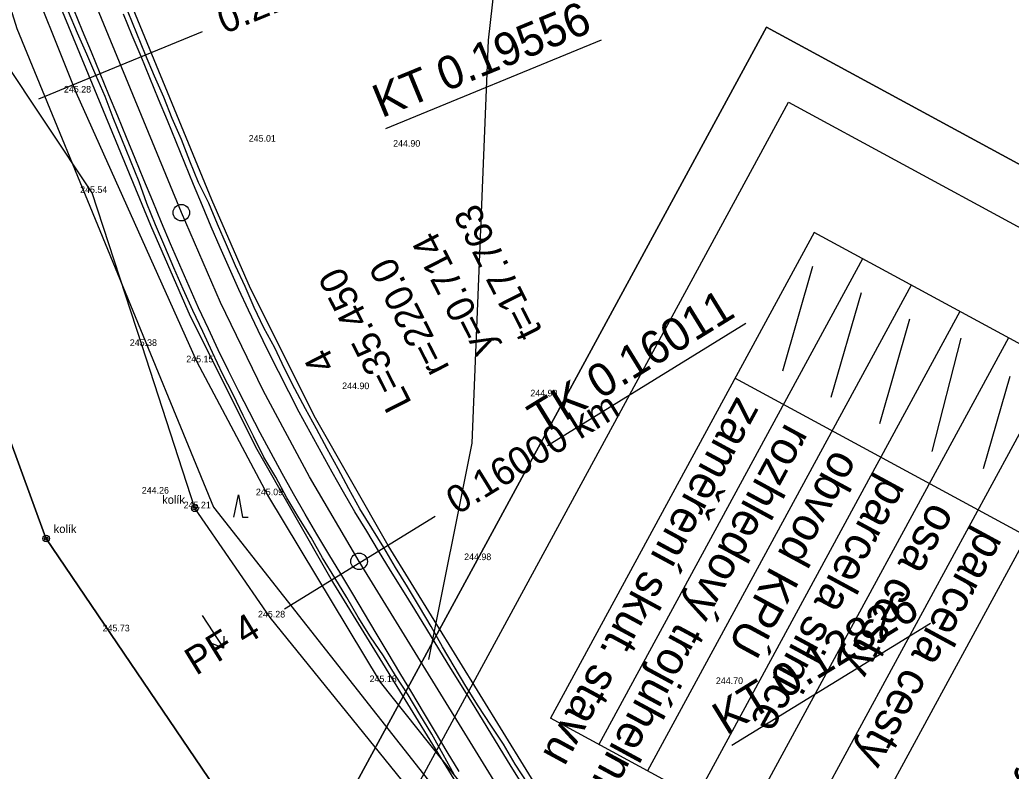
# Model space of a CAD drawing. Extents: x -555887 to -552101, y -1100251 to -1096546.
# Drawn here: x -554132.8 to -554043.2, y -1097201.2 to -1097133.2 of the extents above; entities that cross this region are included whole.
import ezdxf

# ---------------------------------------------------------------- set-up
doc = ezdxf.new("R2010")
doc.units = 0
for name, color, linetype in [('PARCELY_cesty', 7, 'Continuous'), ('PARCELY_VHO', 7, 'Continuous'), ('POLYGONY_SITUACE_PF', 7, 'Continuous'), ('POLYGONY_SITUACE_PF_POPISY', 7, 'Continuous'), ('POLYGONY_SITUACE_PO', 7, 'Continuous'), ('ROZHLED_ram_legenda_1', 7, 'Continuous'), ('vrstevnice', 7, 'Continuous'), ('Výškopis', 7, 'Continuous'), ('ZSST', 7, 'Continuous'), ('zájem', 7, 'Continuous')]:
    doc.layers.add(name, color=color, linetype=linetype)

msp = doc.modelspace()

# ---------------------------------------------------------------- linework, layer by layer
for p, q in [((-554099.718, -1097143.003), (-554080.214, -1097134.973)), ((-554085.106, -1097171.688), (-554067.143, -1097160.633)), ((-554068.416, -1097198.809), (-554050.452, -1097187.754))]:
    msp.add_line(p, q)
at = {"layer": 'PARCELY_cesty'}
for points in [[(-554039.52, -1097311.76), (-554047.31, -1097302.68), (-554067.59, -1097264.38), (-554070.02, -1097259.26), (-554071.42, -1097254.1), (-554072.18, -1097247.42), (-554073.837, -1097234.701), (-554074.64, -1097229.027), (-554076.858, -1097220.767), (-554079.626, -1097213.575), (-554082.86, -1097207.774), (-554099.501, -1097180.734), (-554106.075, -1097169.208), (-554111.955, -1097157.47), (-554115.449, -1097149.447), (-554124.686, -1097127.011)], [(-554038.74, -1097323.54), (-554046.65, -1097316.45), (-554056.115, -1097302.24), (-554073.622, -1097267.292), (-554075.994, -1097261.695), (-554077.187, -1097257.67), (-554078.248, -1097251.684), (-554079.797, -1097235.406), (-554080.53, -1097230.23), (-554082.571, -1097222.628), (-554085.074, -1097216.125), (-554088.037, -1097210.809), (-554104.663, -1097183.794), (-554111.367, -1097172.04), (-554117.392, -1097160.013), (-554120.974, -1097151.787), (-554130.309, -1097129.113)]]:
    msp.add_lwpolyline(points, dxfattribs=at)
at = {"layer": 'PARCELY_VHO'}
for points in [[(-553890.36, -1097670.23), (-553902.88, -1097642.35), (-553905.32, -1097611.67), (-553898.3, -1097524.98), (-553901.53, -1097506.94), (-553991.85, -1097382.83), (-554027.72, -1097360.75), (-554038.93, -1097345.45), (-554044.87, -1097337.64), (-554055.91, -1097333.12), (-554068.1, -1097310.12), (-554076.3, -1097297.37), (-554083.64, -1097283.44), (-554094.93, -1097256.14), (-554100.02, -1097244.94), (-554114.01, -1097204.34), (-554130.46, -1097180.06), (-554159.17, -1097101.34)], [(-554141.5, -1097107.04), (-554133.09, -1097133.96), (-554115.31, -1097177.28), (-554094.19, -1097204.11), (-554083.82, -1097222.99), (-554081.04, -1097249.03), (-554076.85, -1097264.17), (-554065.58, -1097288.03), (-554046.65, -1097316.45), (-554038.74, -1097323.54), (-554028.81, -1097333.03), (-554018.781, -1097341.326), (-554015.89, -1097351.24), (-554008.949, -1097355.38), (-553990.01, -1097365.499), (-553983.508, -1097370.361), (-553977.642, -1097376.021), (-553888.1, -1097498.254), (-553882.924, -1097507.258), (-553879.092, -1097522.388), (-553886.84, -1097615.05), (-553883.68, -1097641.57), (-553876.67, -1097669.5)]]:
    msp.add_lwpolyline(points, dxfattribs=at)
at = {"layer": 'POLYGONY_SITUACE_PF'}
for p, q in [((-554123.709, -1097137.263), (-554116.312, -1097134.218)), ((-554131.107, -1097140.309), (-554123.709, -1097137.263)), ((-554102.082, -1097182.264), (-554095.269, -1097178.071)), ((-554108.895, -1097186.457), (-554102.082, -1097182.264))]:
    msp.add_line(p, q, dxfattribs=at)
at = {"layer": 'POLYGONY_SITUACE_PO'}
for p, q in [((-554118.212, -1097150.617), (-554127.498, -1097128.062)), ((-554127.607, -1097134.362), (-554128.42, -1097132.444)), ((-554127.145, -1097134.172), (-554127.938, -1097132.245)), ((-554122.653, -1097134.576), (-554123.446, -1097132.649)), ((-554122.653, -1097134.576), (-554123.446, -1097132.649)), ((-554122.236, -1097134.404), (-554123.016, -1097132.472)), ((-554126.767, -1097136.269), (-554127.607, -1097134.362)), ((-554126.352, -1097136.098), (-554127.145, -1097134.172)), ((-554121.455, -1097136.335), (-554122.236, -1097134.404)), ((-554121.86, -1097136.502), (-554122.653, -1097134.576)), ((-554121.86, -1097136.502), (-554122.653, -1097134.576)), ((-554125.953, -1097138.187), (-554126.767, -1097136.269)), ((-554125.559, -1097138.025), (-554126.352, -1097136.098)), ((-554120.641, -1097138.253), (-554121.455, -1097136.335)), ((-554121.067, -1097138.428), (-554121.86, -1097136.502)), ((-554121.067, -1097138.428), (-554121.86, -1097136.502)), ((-554124.765, -1097139.951), (-554125.559, -1097138.025)), ((-554125.116, -1097140.095), (-554125.953, -1097138.187)), ((-554120.274, -1097140.355), (-554121.067, -1097138.428)), ((-554120.274, -1097140.355), (-554121.067, -1097138.428)), ((-554119.803, -1097140.161), (-554120.641, -1097138.253)), ((-554124.385, -1097142.048), (-554125.116, -1097140.095)), ((-554123.972, -1097141.878), (-554124.765, -1097139.951)), ((-554119.48, -1097142.281), (-554120.274, -1097140.355)), ((-554119.48, -1097142.281), (-554120.274, -1097140.355)), ((-554119.039, -1097142.1), (-554119.803, -1097140.161)), ((-554123.598, -1097143.976), (-554124.385, -1097142.048)), ((-554123.179, -1097143.804), (-554123.972, -1097141.878)), ((-554118.687, -1097144.208), (-554119.48, -1097142.281)), ((-554118.687, -1097144.208), (-554119.48, -1097142.281)), ((-554118.207, -1097144.01), (-554119.039, -1097142.1)), ((-554122.809, -1097145.905), (-554123.598, -1097143.976)), ((-554122.386, -1097145.731), (-554123.179, -1097143.804)), ((-554117.894, -1097146.134), (-554118.687, -1097144.208)), ((-554117.894, -1097146.134), (-554118.687, -1097144.208)), ((-554117.439, -1097145.947), (-554118.207, -1097144.01)), ((-554122.018, -1097147.832), (-554122.809, -1097145.905)), ((-554121.593, -1097147.657), (-554122.386, -1097145.731)), ((-554117.101, -1097148.061), (-554117.894, -1097146.134)), ((-554117.101, -1097148.061), (-554117.894, -1097146.134)), ((-554116.652, -1097147.876), (-554117.439, -1097145.947)), ((-554121.326, -1097149.8), (-554122.018, -1097147.832)), ((-554120.8, -1097149.584), (-554121.593, -1097147.657)), ((-554115.733, -1097149.749), (-554116.652, -1097147.876)), ((-554116.308, -1097149.986), (-554117.101, -1097148.061)), ((-554116.308, -1097149.986), (-554117.101, -1097148.061)), ((-554120.006, -1097151.511), (-554120.8, -1097149.584)), ((-554114.945, -1097151.65), (-554115.733, -1097149.749)), ((-554120.54, -1097151.731), (-554121.326, -1097149.8)), ((-554114.674, -1097158.742), (-554118.212, -1097150.617)), ((-554115.512, -1097151.89), (-554116.308, -1097149.986)), ((-554115.512, -1097151.89), (-554116.308, -1097149.986)), ((-554119.195, -1097153.451), (-554120.006, -1097151.511)), ((-554119.721, -1097153.674), (-554120.54, -1097151.731)), ((-554114.695, -1097153.786), (-554115.512, -1097151.89)), ((-554114.695, -1097153.786), (-554115.512, -1097151.89)), ((-554114.13, -1097153.541), (-554114.945, -1097151.65)), ((-554118.881, -1097155.607), (-554119.721, -1097153.674)), ((-554118.364, -1097155.381), (-554119.195, -1097153.451)), ((-554113.862, -1097155.675), (-554114.695, -1097153.786)), ((-554113.862, -1097155.675), (-554114.695, -1097153.786)), ((-554113.321, -1097155.434), (-554114.13, -1097153.541)), ((-554118.049, -1097157.543), (-554118.881, -1097155.607)), ((-554117.515, -1097157.305), (-554118.364, -1097155.381)), ((-554113.016, -1097157.558), (-554113.862, -1097155.675)), ((-554113.016, -1097157.558), (-554113.862, -1097155.675)), ((-554112.434, -1097157.292), (-554113.321, -1097155.434)), ((-554117.18, -1097159.464), (-554118.049, -1097157.543)), ((-554116.653, -1097159.222), (-554117.515, -1097157.305)), ((-554112.145, -1097159.43), (-554113.016, -1097157.558)), ((-554112.145, -1097159.43), (-554113.016, -1097157.558)), ((-554111.636, -1097159.191), (-554112.434, -1097157.292)), ((-554110.811, -1097166.717), (-554114.674, -1097158.742)), ((-554116.275, -1097161.367), (-554117.18, -1097159.464)), ((-554115.767, -1097161.129), (-554116.653, -1097159.222)), ((-554111.263, -1097161.296), (-554112.145, -1097159.43)), ((-554111.263, -1097161.296), (-554112.145, -1097159.43)), ((-554110.756, -1097161.053), (-554111.636, -1097159.191)), ((-554115.387, -1097163.278), (-554116.275, -1097161.367)), ((-554114.868, -1097163.029), (-554115.767, -1097161.129)), ((-554110.356, -1097163.151), (-554111.263, -1097161.296)), ((-554110.356, -1097163.151), (-554111.263, -1097161.296)), ((-554109.772, -1097162.864), (-554110.756, -1097161.053)), ((-554113.945, -1097164.918), (-554114.868, -1097163.029)), ((-554109.435, -1097164.998), (-554110.356, -1097163.151)), ((-554109.435, -1097164.998), (-554110.356, -1097163.151)), ((-554108.868, -1097164.713), (-554109.772, -1097162.864)), ((-554114.502, -1097165.192), (-554115.387, -1097163.278)), ((-554113.007, -1097166.799), (-554113.945, -1097164.918)), ((-554108.504, -1097166.841), (-554109.435, -1097164.998)), ((-554108.504, -1097166.841), (-554109.435, -1097164.998)), ((-554107.951, -1097166.556), (-554108.868, -1097164.713)), ((-554113.531, -1097167.063), (-554114.502, -1097165.192)), ((-554112.059, -1097168.675), (-554113.007, -1097166.799)), ((-554106.631, -1097174.531), (-554110.811, -1097166.717)), ((-554106.973, -1097168.367), (-554107.951, -1097166.556)), ((-554112.632, -1097168.971), (-554113.531, -1097167.063)), ((-554107.543, -1097168.668), (-554108.504, -1097166.841)), ((-554107.543, -1097168.668), (-554108.504, -1097166.841)), ((-554106.002, -1097170.182), (-554106.973, -1097168.367)), ((-554111.678, -1097170.851), (-554112.632, -1097168.971)), ((-554111.08, -1097170.536), (-554112.059, -1097168.675)), ((-554106.571, -1097170.489), (-554107.543, -1097168.668)), ((-554106.571, -1097170.489), (-554107.543, -1097168.668)), ((-554105.013, -1097171.987), (-554106.002, -1097170.182)), ((-554110.765, -1097172.755), (-554111.678, -1097170.851)), ((-554110.09, -1097172.391), (-554111.08, -1097170.536)), ((-554105.581, -1097172.301), (-554106.571, -1097170.489)), ((-554105.581, -1097172.301), (-554106.571, -1097170.489)), ((-554104.025, -1097173.792), (-554105.013, -1097171.987)), ((-554109.68, -1097174.566), (-554110.765, -1097172.755)), ((-554109.082, -1097174.235), (-554110.09, -1097172.391)), ((-554104.572, -1097174.102), (-554105.581, -1097172.301)), ((-554104.572, -1097174.102), (-554105.581, -1097172.301)), ((-554103.052, -1097175.608), (-554104.025, -1097173.792)), ((-554108.657, -1097176.41), (-554109.68, -1097174.566)), ((-554108.055, -1097176.069), (-554109.082, -1097174.235)), ((-554102.139, -1097182.17), (-554106.631, -1097174.531)), ((-554103.552, -1097175.897), (-554104.572, -1097174.102)), ((-554103.552, -1097175.897), (-554104.572, -1097174.102)), ((-554102.065, -1097177.416), (-554103.052, -1097175.608)), ((-554107.585, -1097178.226), (-554108.657, -1097176.41)), ((-554107.016, -1097177.897), (-554108.055, -1097176.069)), ((-554102.51, -1097177.679), (-554103.552, -1097175.897)), ((-554102.51, -1097177.679), (-554103.552, -1097175.897)), ((-554100.995, -1097179.175), (-554102.065, -1097177.416)), ((-554106.481, -1097180.022), (-554107.585, -1097178.226)), ((-554105.955, -1097179.712), (-554107.016, -1097177.897)), ((-554101.45, -1097179.45), (-554102.51, -1097177.679)), ((-554101.45, -1097179.45), (-554102.51, -1097177.679)), ((-554099.903, -1097180.923), (-554100.995, -1097179.175)), ((-554105.434, -1097181.853), (-554106.481, -1097180.022)), ((-554104.875, -1097181.516), (-554105.955, -1097179.712)), ((-554100.378, -1097181.216), (-554101.45, -1097179.45)), ((-554100.378, -1097181.216), (-554101.45, -1097179.45)), ((-554098.839, -1097182.714), (-554099.903, -1097180.923)), ((-554104.334, -1097183.65), (-554105.434, -1097181.853)), ((-554103.786, -1097183.313), (-554104.875, -1097181.516)), ((-554099.287, -1097182.99), (-554100.378, -1097181.216)), ((-554099.287, -1097182.99), (-554100.378, -1097181.216)), ((-554085.449, -1097209.291), (-554102.139, -1097182.17)), ((-554097.751, -1097184.491), (-554098.839, -1097182.714)), ((-554103.25, -1097185.429), (-554104.334, -1097183.65)), ((-554102.717, -1097185.101), (-554103.786, -1097183.313)), ((-554098.195, -1097184.764), (-554099.287, -1097182.99)), ((-554098.195, -1097184.764), (-554099.287, -1097182.99)), ((-554096.681, -1097186.279), (-554097.751, -1097184.491)), ((-554102.211, -1097187.236), (-554103.25, -1097185.429)), ((-554101.647, -1097186.889), (-554102.717, -1097185.101)), ((-554097.103, -1097186.538), (-554098.195, -1097184.764)), ((-554097.103, -1097186.538), (-554098.195, -1097184.764)), ((-554096.011, -1097188.313), (-554097.103, -1097186.538)), ((-554096.011, -1097188.313), (-554097.103, -1097186.538)), ((-554095.613, -1097188.068), (-554096.681, -1097186.279)), ((-554101.093, -1097188.994), (-554102.211, -1097187.236)), ((-554100.577, -1097188.677), (-554101.647, -1097186.889)), ((-554094.919, -1097190.087), (-554096.011, -1097188.313)), ((-554094.919, -1097190.087), (-554096.011, -1097188.313)), ((-554094.604, -1097189.893), (-554095.613, -1097188.068)), ((-554099.928, -1097190.723), (-554101.093, -1097188.994)), ((-554099.508, -1097190.465), (-554100.577, -1097188.677)), ((-554093.827, -1097191.861), (-554094.919, -1097190.087)), ((-554093.827, -1097191.861), (-554094.919, -1097190.087)), ((-554093.547, -1097191.689), (-554094.604, -1097189.893)), ((-554098.854, -1097192.509), (-554099.928, -1097190.723)), ((-554098.438, -1097192.253), (-554099.508, -1097190.465)), ((-554092.735, -1097193.635), (-554093.827, -1097191.861)), ((-554092.735, -1097193.635), (-554093.827, -1097191.861)), ((-554092.483, -1097193.48), (-554093.547, -1097191.689)), ((-554097.698, -1097194.243), (-554098.854, -1097192.509)), ((-554097.368, -1097194.041), (-554098.438, -1097192.253)), ((-554091.643, -1097195.41), (-554092.735, -1097193.635)), ((-554091.643, -1097195.41), (-554092.735, -1097193.635)), ((-554091.368, -1097195.24), (-554092.483, -1097193.48)), ((-554096.638, -1097196.037), (-554097.698, -1097194.243)), ((-554096.299, -1097195.829), (-554097.368, -1097194.041)), ((-554090.551, -1097197.184), (-554091.643, -1097195.41)), ((-554090.551, -1097197.184), (-554091.643, -1097195.41)), ((-554090.219, -1097196.979), (-554091.368, -1097195.24)), ((-554095.56, -1097197.82), (-554096.638, -1097196.037)), ((-554095.229, -1097197.617), (-554096.299, -1097195.829)), ((-554089.459, -1097198.958), (-554090.551, -1097197.184)), ((-554089.459, -1097198.958), (-554090.551, -1097197.184)), ((-554089.084, -1097198.727), (-554090.219, -1097196.979)), ((-554094.54, -1097199.639), (-554095.56, -1097197.82)), ((-554094.16, -1097199.405), (-554095.229, -1097197.617)), ((-554088.367, -1097200.732), (-554089.459, -1097198.958)), ((-554088.367, -1097200.732), (-554089.459, -1097198.958)), ((-554088.025, -1097200.522), (-554089.084, -1097198.727)), ((-554093.538, -1097201.468), (-554094.54, -1097199.639)), ((-554093.09, -1097201.193), (-554094.16, -1097199.405)), ((-554087.275, -1097202.507), (-554088.367, -1097200.732)), ((-554087.275, -1097202.507), (-554088.367, -1097200.732)), ((-554086.871, -1097202.258), (-554088.025, -1097200.522))]:
    msp.add_line(p, q, dxfattribs=at)
for centre in [(-554118.212, -1097150.617), (-554102.139, -1097182.17)]:
    msp.add_circle(centre, 0.75, dxfattribs=at)
at = {"layer": 'ROZHLED_ram_legenda_1'}
for p, q in [((-554060.985, -1097152.407), (-554084.834, -1097196.353)), ((-554034.618, -1097166.716), (-554060.985, -1097152.407)), ((-554056.591, -1097154.792), (-554080.439, -1097198.738)), ((-554061.133, -1097155.496), (-554063.851, -1097164.967)), ((-554052.196, -1097157.177), (-554076.045, -1097201.123)), ((-554056.739, -1097157.881), (-554059.456, -1097167.351)), ((-554047.802, -1097159.562), (-554071.65, -1097203.508)), ((-554052.344, -1097160.265), (-554055.062, -1097169.736)), ((-554043.407, -1097161.946), (-554067.255, -1097205.893)), ((-554047.721, -1097161.989), (-554050.328, -1097172.243)), ((-554039.012, -1097164.331), (-554062.861, -1097208.277)), ((-554041.772, -1097179.9), (-554068.14, -1097165.591)), ((-554043.277, -1097165.458), (-554045.683, -1097173.79)), ((-554034.618, -1097166.716), (-554058.466, -1097210.662)), ((-554058.466, -1097210.662), (-554084.834, -1097196.353))]:
    msp.add_line(p, q, dxfattribs=at)
msp.add_lwpolyline([(-554022.385, -1097495.033), (-554206.959, -1097394.87), (-554065.3, -1097133.83), (-553880.726, -1097233.993)], close=True, dxfattribs=at)
msp.add_lwpolyline([(-554022.385, -1097495.033), (-554206.959, -1097394.87), (-554065.3, -1097133.83), (-553880.726, -1097233.993)], close=True, dxfattribs=at)
for points in [[(-553880.726, -1097233.993), (-554065.3, -1097133.83), (-554206.959, -1097394.87), (-554022.385, -1097495.033), (-553880.726, -1097233.993)], [(-554200.18, -1097392.86), (-554063.29, -1097140.609), (-553887.506, -1097236.003), (-554024.395, -1097488.253), (-554200.18, -1097392.86)], [(-554200.18, -1097392.86), (-554063.29, -1097140.609), (-553887.506, -1097236.003), (-554024.395, -1097488.253), (-554200.18, -1097392.86)]]:
    msp.add_lwpolyline(points, dxfattribs=at)
at = {"layer": 'vrstevnice'}
msp.add_lwpolyline([(-554095.816, -1097191.043), (-554091.899, -1097171.48), (-554090.439, -1097135.02), (-554088.389, -1097116.86)], dxfattribs=at)
at = {"layer": 'ZSST'}
for p, q in [((-554113.467, -1097178.162), (-554113.056, -1097176.164)), ((-554113.056, -1097176.164), (-554112.667, -1097178.166)), ((-554112.667, -1097178.166), (-554112.167, -1097178.169)), ((-554116.319, -1097187.083), (-554114.408, -1097190.015)), ((-554114.362, -1097188.948), (-554114.408, -1097190.015)), ((-554114.408, -1097190.015), (-554115.403, -1097189.626))]:
    msp.add_line(p, q, dxfattribs=at)
for points in [[(-554056.9, -1097304), (-554063.52, -1097293.03), (-554074.17, -1097274.2), (-554078.71, -1097261.75), (-554082.34, -1097246.77), (-554082.1, -1097236.17), (-554084.78, -1097223.3), (-554095.29, -1097205.66), (-554110.17, -1097187.25), (-554117, -1097177.37), (-554121.76, -1097162.68), (-554126.27, -1097148.83), (-554134.49, -1097136.49), (-554138.97, -1097119.53)], [(-554043.64, -1097319), (-554047.77, -1097318.58), (-554052.74, -1097314.07), (-554056.9, -1097304), (-554062.41, -1097287), (-554068.66, -1097272.27), (-554076.19, -1097251.39), (-554079.41, -1097237.5), (-554082.27, -1097222.72), (-554086.75, -1097212.07), (-554091.28, -1097204.32), (-554100.2, -1097193.1), (-554110.38, -1097176.19), (-554116.77, -1097164.16), (-554127.72, -1097139.75), (-554132.59, -1097127.58)]]:
    msp.add_lwpolyline(points, dxfattribs=at)
for centre, radius in [((-554117, -1097177.37), 0.3), ((-554117, -1097177.37), 0.15), ((-554130.44, -1097180.11), 0.3), ((-554130.44, -1097180.11), 0.15)]:
    msp.add_circle(centre, radius, dxfattribs=at)
at = {"layer": 'zájem'}
for points in [[(-554209.05, -1097338.04), (-554121.59, -1097427.95), (-554119.85, -1097429.74), (-554117.62, -1097427.68), (-554074.61, -1097473), (-554067.74, -1097480.24), (-554074.25, -1097435.16), (-554074.7, -1097411.2), (-554072.86, -1097396.87), (-554069.61, -1097384.37), (-554062.54, -1097368.79), (-554059.66, -1097363.67), (-554044.87, -1097337.64), (-554055.91, -1097333.12), (-554068.1, -1097310.12), (-554076.3, -1097297.37), (-554083.64, -1097283.44), (-554094.93, -1097256.14), (-554100.02, -1097244.94), (-554114.01, -1097204.34), (-554130.46, -1097180.06), (-554159.17, -1097101.34)], [(-554159.17, -1097101.34), (-554130.46, -1097180.06), (-554114.01, -1097204.34), (-554100.02, -1097244.94), (-554094.93, -1097256.14), (-554083.64, -1097283.44), (-554076.3, -1097297.37), (-554068.1, -1097310.12), (-554055.91, -1097333.12), (-554044.87, -1097337.64), (-554059.66, -1097363.67), (-554062.54, -1097368.79), (-554069.61, -1097384.37), (-554072.86, -1097396.87), (-554074.7, -1097411.2), (-554074.25, -1097435.16), (-554067.74, -1097480.24), (-554074.61, -1097473), (-554117.62, -1097427.68), (-554119.85, -1097429.74), (-554121.59, -1097427.95), (-554209.05, -1097338.04)]]:
    msp.add_lwpolyline(points, dxfattribs=at)

# ---------------------------------------------------------------- texts
for s, height, rotation, p in [('KT 0.19556', 3, 22.37662, (-554100.098, -1097142.078)), ('t=17.763', 2.5, 116.9928, (-554085.506, -1097161.317)), ('y=0.714', 2.5, 116.9928, (-554089.786, -1097162.828)), ('r=220.0', 2.5, 116.9928, (-554093.91, -1097164.647)), ('L=35.450', 2.5, 116.9928, (-554097.326, -1097167.855)), ('TK 0.16011', 3, 31.60897, (-554085.631, -1097170.836)), ('4', 2.5, 116.9928, (-554104.146, -1097164.38)), ('KT 0.12826', 3, 31.60897, (-554068.94, -1097197.957))]:
    msp.add_text(s, height=height, rotation=rotation).set_placement(p)
at = {"layer": 'POLYGONY_SITUACE_PF_POPISY'}
for s, rotation, p in [('0.21000 km', 22.37662, (-554114.31, -1097134.475)), ('0.16000 km', 31.60897, (-554093.252, -1097178.004)), ('PF 4', 31.60897, (-554116.887, -1097192.55))]:
    msp.add_text(s, height=2.5, rotation=rotation, dxfattribs=at).set_placement(p)
at = {"layer": 'ROZHLED_ram_legenda_1'}
for s, height, p in [('zaměření skut. stavu', 2.99999, (-554067.939, -1097167.152)), ('rozhledový trojúhelník', 2.99999, (-554063.544, -1097169.537)), ('Rozhledové poměry jsou vyhovující', 2.99999, (-554025.762, -1097171.51)), ('obvod KPÚ', 3, (-554059.15, -1097171.921)), ('l=3m (od hrany zpevnění komunikace)', 2.99999, (-554021.658, -1097173.738)), ('parcela silnice', 2.99999, (-554054.755, -1097174.306)), ('osa cesty', 3, (-554050.361, -1097176.691)), ('parcela cesty', 2.99999, (-554045.966, -1097179.076))]:
    msp.add_text(s, height=height, rotation=241.51256, dxfattribs=at).set_placement(p)
at = {"layer": 'Výškopis'}
for s, p in [('245.28', (-554128.83, -1097139.75)), ('245.01', (-554112.118, -1097144.2)), ('244.90', (-554099.057, -1097144.65)), ('245.54', (-554127.366, -1097148.83)), ('245.38', (-554122.874, -1097162.68)), ('245.15', (-554117.764, -1097164.16)), ('244.90', (-554103.667, -1097166.59)), ('244.90', (-554086.647, -1097167.25)), ('244.26', (-554121.79, -1097176.04)), ('245.09', (-554111.47, -1097176.19)), ('245.21', (-554118.002, -1097177.37)), ('244.98', (-554092.635, -1097182.06)), ('245.28', (-554111.28, -1097187.25)), ('245.73', (-554125.336, -1097188.51)), ('245.18', (-554101.186, -1097193.1)), ('244.70', (-554069.865, -1097193.27))]:
    msp.add_text(s, height=0.6, dxfattribs=at).set_placement(p)
at = {"layer": 'ZSST'}
for p in [(-554119.949, -1097176.965), (-554129.755, -1097179.611)]:
    msp.add_text('kolík', height=0.75, dxfattribs=at).set_placement(p)

doc.saveas('drawing.dxf')
